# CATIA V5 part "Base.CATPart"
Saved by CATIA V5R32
Part number: Part1
Bounding box of the stored display mesh (mm): x -50 to 50, y -25 to 25, z 0 to 50
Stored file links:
  D:\PROJECTS\Project 2022\CATIA V5 6R 2022\Resources\Part Files\c12_catia_v5_6r2022_prt\c12_catia_v5-6r2022 figr_12-15\Base.CATPart
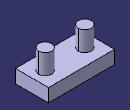
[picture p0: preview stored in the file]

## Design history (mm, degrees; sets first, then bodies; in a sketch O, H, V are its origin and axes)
Body1 (main body)
  Sketch1 on xy-plane, origin (0, 0, 0), H (1, 0, 0), V (0, 1, 0)
    line L1 (50, 25) -> (50, -25)
    line L2 (50, -25) -> (-50, -25)
    line L3 (-50, -25) -> (-50, 25)
    line L4 (-50, 25) -> (50, 25)
    circle A1 centre (-30, 0) radius 10
    point P5 (-30, 0)
    circle A2 centre (30, 0) radius 10
    length L2 = 100
    length L1 = 50
    radius A1 = 10
    distance P5 V = 30
    vertical: L1 V, L3 V
    horizontal: L2 H, L4 H
    equidistance: L1 L3 O, L2 L4 O
    coincidence: P5 H
    symmetry: A1 A2 V
  MultiPad1: profile Sketch1, domains (length 20; length 50; length 50)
